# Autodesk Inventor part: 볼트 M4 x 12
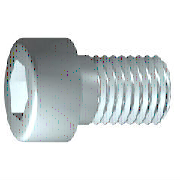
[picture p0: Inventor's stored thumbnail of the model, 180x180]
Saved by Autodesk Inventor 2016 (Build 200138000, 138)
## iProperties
IsCustomPart: 0
Created: 2012-02
Part Number: 볼트 M4 x 12
Material: 강철, 연강
Description: 6각 소켓 머리 캡 나사
Document SubType Name: Modeling
Standard: ISO 4762
Designer: mduedu
Standard Revision: Fourth edition 2004-03-01
Standards Organization: ISO
Language: ko-KR
Size Designation: M4 x 12
Categories: <MemberInstance><Categories><Category DisplayName="조임쇠" InternalName="e4da775c-781d-43d5-af7c-5136215cf5a6" Mnemonic="FSTN"><Category DisplayName="볼트" InternalN
Density: 7.75 g/cm^3
Appearance: 강철
Author: mduedu
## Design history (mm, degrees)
sketch "스케치1"
  geometry: L1 (-1, 0)-(12, 0); L2 (12, 0)-(12, 2); L3 (12, 2)-(1.75, 2); L4 (1.75, 2)-(1.32, 2); L5 (1.32, 2)-(0, 2); L6 (0, 2)-(0, 3.5); L7 (0, 3.5)-(-4, 3.5); L8 (-4, 3.5)-(-4, 1.732); L9 (-4, 1.732)-(-2, 1.732); L10 (-2, 1.732)-(-1, 0); L11 (-7.2, 0)-(15.2, 0) reference; L12 (0, -0.7)-(0, 4.2) reference; L13 (1.75, 2)-(0, 2)
  constraints: 22 end point, 6 parallel, 2 collinear, 2 perpendicular, 1 horizontal, 1 point on line
  dimensions: "d1" = 10.25 distance from line of L3.end L2 (= GEL); "d2" = 0.42952 distance of L4.end L3.end (computed from GAL); "d3" = 4 distance between parallel lines of L8 L6 (= KOH); "d4" = 2 distance of L8.end L9.end (= INTI); "d5" = 60 deg angle of L10 L1; "d6" = 4 diameter of L3 L1 (= GD); "d7" = 4 diameter of L5 L1 (= BDM); "d8" = 3.4641 diameter of L9 L1 (= 1.1547 x SW); "d9" = 7 diameter of L7 L1 (= KOD); "d26" = 12 distance between parallel lines of L12 L2 (= NLG)
revolve "본체" sketch "스케치1" stored, may be unused: angle "d10" = 90 deg
sketch "스케치2"
  geometry: L1 (0, -4.9)-(0, 4.9) reference; L2 (-4.9, 0)-(4.9, 0) reference; L3 (1.732, 0)-(0.866, -1.5); L4 (0.866, -1.5)-(-0.866, -1.5); L5 (-0.866, -1.5)-(-1.732, 0); L6 (-1.732, 0)-(-0.866, 1.5); L7 (-0.866, 1.5)-(0.866, 1.5); L8 (0.866, 1.5)-(1.732, 0); 2 further points
  constraints: 12 end point, 1 coincident, 1 horizontal alignment, 1 point on line, 12 other
extrude "슬롯" join sketch "스케치2" stored distance "d11" = 10; taper "d12" = 0 deg
workplane "Work Plane1"
fillet "Fillet2" dims "d30" = 0.1 (= R)
body "Solid1"
fillet "모깎기1" dims "d17" = 0.4 (= RR)
feature "스레드" dims "d13" = 10.25 (= GEL), "d14" = 0
chamfer "모따기1" distance "d15" = 0.42941 (= -0.5 x SPD + 0.5 x GD); stored, may be unused: second distance "d16" = 0.42941 (= GUL), angle "d27" = 45 deg
other parameters: "GD" = 4 [user parameter; used in 2 equation terms], "NLG" = 12 [user parameter; used in 1 equation term], "GEL" = 10.25 [user parameter; used in 2 equation terms], "KOD" = 7 [user parameter; used in 1 equation term], "KOH" = 4 [user parameter; used in 1 equation term], "INTI" = 2 [user parameter; used in 1 equation term], "GAL" = 0.42941 (= 0.61345 x PTC) [user parameter; used in 1 equation term], "GUL" = 0.42941 (= 0.61345 x PTC) [user parameter; used in 1 equation term], "BDM" = 4 (= NND) [user parameter; used in 1 equation term], "SW" = 3 [user parameter; used in 2 equation terms], "RR" = 0.4 [user parameter; used in 1 equation term], "SPD" = 3.14117 (= NND - 1.2269 x PTC) [user parameter; used in 1 equation term], "d19" = 0, "d28" = 0, "d29" = 0, "R" = 0.1 [user parameter; used in 1 equation term], "TOA" = 30 deg [user parameter], "GD1" = 3.14117 (= THREADDIA - 1.2269 x PTC) [user parameter], "THREADDIA" = 4 [user parameter; used in 1 equation term], "FAWI" = 45 deg [user parameter], "TPU" = 14.28571 (computed from PTC) [user parameter], "PTC" = 0.7 [user parameter; used in 5 equation terms], "NND" = 4 [user parameter; used in 2 equation terms], "E0" = 3.465 (= 1.155 x SW) [user parameter]
